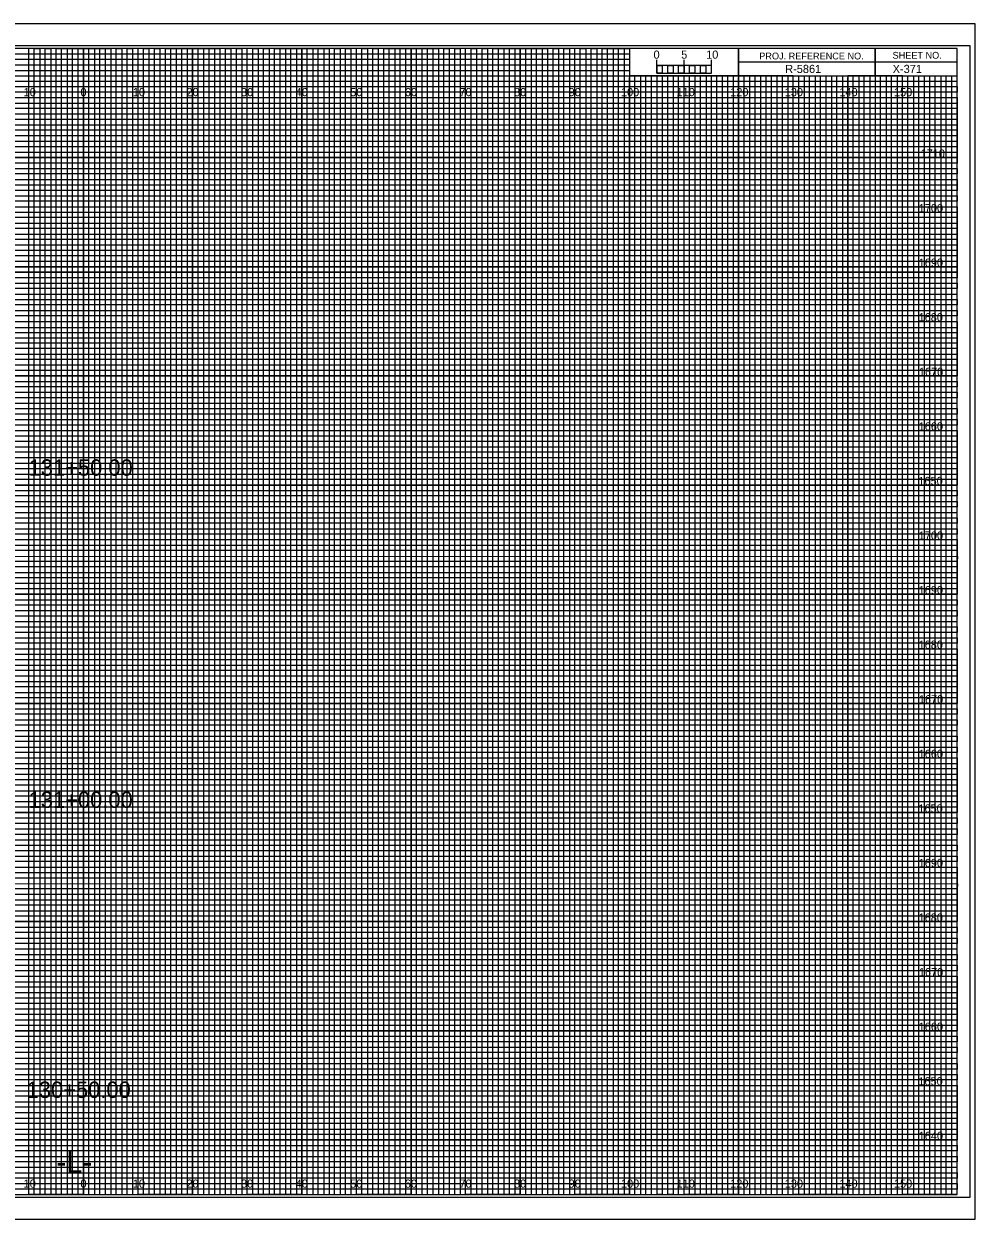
# Model space of a CAD drawing. Extents: x -13 to 323, y -5 to 2414.
# Drawn here: x 149.1 to 323.3, y 1535.5 to 1754.5 of the extents above; entities that cross this region are included whole.
import ezdxf

# ---------------------------------------------------------------- set-up
doc = ezdxf.new("R2010")
doc.units = 0
for name, color, linetype in [('Prop XS Alignment Label', 7, 'Continuous'), ('Prop XS Bar Scale Labels', 7, 'Continuous'), ('Prop XS Elevation Labels', 7, 'Continuous'), ('Prop XS Offset Labels', 7, 'Continuous'), ('Prop XS Project Number', 7, 'Continuous'), ('Prop XS Sheet Number', 7, 'Continuous'), ('Prop XS Station Labels', 7, 'Continuous'), ('Sheet Cross Section CELL', 7, 'Continuous'), ('Sheet Cross Section Grid Major CELL', 7, 'Continuous'), ('Sheet Cross Section Grid Middle CELL', 7, 'Continuous'), ('Sheet Cross Section Grid Minor 1 CELL', 7, 'Continuous'), ('Sheet Cross Section Grid Minor 2 CELL', 7, 'Continuous'), ('Sheet Cross Section Scale CELL', 7, 'Continuous'), ('Sheet Cutting Line CELL', 7, 'Continuous'), ('Sheet DOT Grid CELL', 7, 'Continuous'), ('Sheet Plot Border Inside CELL', 7, 'Continuous'), ('Sheet Plot Border Outside CELL', 7, 'Continuous')]:
    doc.layers.add(name, color=color, linetype=linetype)

msp = doc.modelspace()

# ---------------------------------------------------------------- linework, layer by layer
at = {"layer": 'Sheet Cross Section CELL'}
for p, q in [((305, 1750), (305, 1745)), ((305, 1745), (305, 1750)), ((280, 1747.5), (280, 1745)), ((320, 1747.49), (280, 1747.49)), ((280, 1745), (320, 1745))]:
    msp.add_line(p, q, dxfattribs=at)
for points in [[(320, 1750), (0, 1750), (0, 1540), (320, 1540)], [(280, 1750), (260, 1750), (260, 1745.03), (280, 1745.03)], [(320, 1750), (280, 1750), (280, 1745), (320, 1745)]]:
    msp.add_lwpolyline(points, close=True, dxfattribs=at)
at = {"layer": 'Sheet Cross Section Grid Major CELL'}
for p, q in [((150, 1750), (140, 1750)), ((150, 1540), (150, 1750)), ((170, 1750), (160, 1750)), ((160, 1750), (160, 1540)), ((170, 1540), (170, 1750)), ((190, 1750), (180, 1750)), ((180, 1750), (180, 1540)), ((190, 1540), (190, 1750)), ((210, 1750), (200, 1750)), ((200, 1750), (200, 1540)), ((210, 1540), (210, 1750)), ((230, 1750), (220, 1750)), ((220, 1750), (220, 1540)), ((230, 1540), (230, 1750)), ((250, 1750), (240, 1750)), ((240, 1750), (240, 1540)), ((250, 1540), (250, 1750)), ((260, 1750), (260, 1540)), ((270, 1540), (270, 1745)), ((290, 1745), (280, 1745)), ((280, 1745), (280, 1540)), ((290, 1540), (290, 1745)), ((310, 1745), (300, 1745)), ((300, 1745), (300, 1540)), ((310, 1540), (310, 1745)), ((160, 1540), (150, 1540)), ((180, 1540), (170, 1540)), ((200, 1540), (190, 1540)), ((220, 1540), (210, 1540)), ((240, 1540), (230, 1540)), ((260, 1540), (250, 1540)), ((280, 1540), (270, 1540)), ((300, 1540), (290, 1540)), ((320, 1540), (310, 1540)), ((320, 1540), (320, 1540))]:
    msp.add_line(p, q, dxfattribs=at)
for points in [[(0, 1740), (320, 1740), (320, 1730), (0, 1730)], [(0, 1720), (320, 1720), (320, 1710), (0, 1710)], [(0, 1700), (320, 1700), (320, 1690), (0, 1690)], [(0, 1680), (320, 1680), (320, 1670), (0, 1670)], [(0, 1660), (320, 1660), (320, 1650), (0, 1650)], [(0, 1640), (320, 1640), (320, 1630), (0, 1630)], [(0, 1620), (320, 1620), (320, 1610), (0, 1610)], [(0, 1600), (320, 1600), (320, 1590), (0, 1590)], [(0, 1580), (320, 1580), (320, 1570), (0, 1570)], [(0, 1560), (320, 1560), (320, 1550), (0, 1550)]]:
    msp.add_lwpolyline(points, dxfattribs=at)
at = {"layer": 'Sheet Cross Section Grid Middle CELL'}
for points in [[(145, 1540), (155, 1540), (155, 1750), (165, 1750), (165, 1540), (175, 1540), (175, 1750), (185, 1750), (185, 1540), (195, 1540), (195, 1750), (205, 1750), (205, 1540), (215, 1540), (215, 1750), (225, 1750), (225, 1540), (235, 1540), (235, 1750), (245, 1750), (245, 1540), (255, 1540), (255, 1750), (259.93, 1750), (260, 1750), (260, 1745), (264.99, 1745), (264.99, 1540), (275, 1540), (275, 1745), (285, 1745), (285, 1540), (295, 1540), (295, 1745), (305, 1745), (305, 1540), (315, 1540), (315, 1745)], [(0, 1745), (275, 1745)], [(0, 1725), (320, 1725), (320, 1735), (0, 1735)], [(0, 1705), (320, 1705), (320, 1715), (0, 1715)], [(0, 1685), (320, 1685), (320, 1695), (0, 1695)], [(0, 1665), (320, 1665), (320, 1675), (0, 1675)], [(0, 1645), (320, 1645), (320, 1655), (0, 1655)], [(0, 1625), (320, 1625), (320, 1635), (0, 1635)], [(0, 1605), (320, 1605), (320, 1615), (0, 1615)], [(0, 1585), (320, 1585), (320, 1595), (0, 1595)], [(0, 1565), (320, 1565), (320, 1575), (0, 1575)], [(0, 1545), (320, 1545), (320, 1555), (0, 1555)]]:
    msp.add_lwpolyline(points, dxfattribs=at)
at = {"layer": 'Sheet Cross Section Grid Minor 1 CELL'}
for p, q in [((0, 1749), (260, 1749)), ((260, 1747.98), (0, 1747.98)), ((260, 1749), (260, 1747.98)), ((0, 1747), (260, 1747)), ((260, 1745.89), (0, 1745.89)), ((260, 1747), (260, 1745.89)), ((0, 1744), (320, 1744))]:
    msp.add_line(p, q, dxfattribs=at)
for points in [[(0, 1743), (270, 1743), (320, 1743), (320, 1742), (0, 1742)], [(0, 1741), (320, 1741), (320, 1739), (0, 1739)], [(0, 1738), (320, 1738), (320, 1737), (0, 1736.98)], [(0, 1736), (320, 1736), (320, 1734), (0, 1734)], [(0, 1733), (320, 1733), (320, 1732), (0, 1732)], [(0, 1731), (320, 1731), (320, 1729), (0, 1729)], [(0, 1728), (320, 1728), (320, 1727), (0, 1727)], [(0, 1726), (320, 1726), (320, 1724), (0, 1724)], [(0, 1723), (320, 1723), (320, 1722), (0, 1722)], [(0, 1721), (320, 1721), (320, 1719), (0, 1719)], [(0, 1718), (320, 1718), (320, 1717), (0, 1717)], [(0, 1716), (320, 1716), (320, 1713.95), (320, 1713), (320, 1712), (0, 1712)], [(0, 1714), (320, 1714), (320, 1713), (0, 1713)], [(0, 1711), (320, 1711), (320, 1709), (0, 1709.03)], [(0, 1709.03), (320, 1709), (320, 1708), (0, 1708)], [(0, 1707), (320, 1707), (320, 1706), (0, 1706)], [(0, 1704), (320, 1704), (320, 1703), (0, 1703)], [(0, 1702), (320, 1702), (320, 1701), (0, 1701)], [(-0.07, 1698.89), (320, 1698.89), (320, 1697.88), (-0.07, 1697.88)], [(0, 1697), (320, 1697), (320, 1696), (0, 1696)], [(0, 1694), (320, 1694), (320, 1693), (0, 1693)], [(0, 1692), (320, 1692), (320, 1691), (0, 1691)], [(0, 1689), (320, 1689), (320, 1688), (0, 1688)], [(0, 1687), (320, 1687), (320, 1686), (0, 1686)], [(0, 1684), (320, 1684), (320, 1683), (0, 1683)], [(0, 1682), (320, 1682), (320, 1681), (0, 1681)], [(0, 1679), (320, 1679), (319.99, 1677.98), (0, 1678)], [(0, 1677), (320, 1677), (320, 1676), (0, 1676)], [(0, 1674), (320, 1674), (320, 1673), (0, 1673)], [(0, 1672), (320, 1672), (320, 1671), (0, 1671)], [(0, 1669), (320, 1669), (320, 1668), (0, 1668)], [(0, 1667), (320, 1667), (320, 1666), (0, 1666)], [(0, 1664), (320, 1664), (320, 1663), (0, 1663)], [(0, 1662), (320, 1662), (320, 1661), (0, 1661)], [(0, 1659), (320, 1659), (320, 1658), (0, 1658)], [(0, 1656.99), (320.07, 1656.91), (320, 1656), (0, 1656)], [(0, 1654), (320, 1654), (320, 1653), (0, 1653)], [(0, 1652), (320, 1652), (320, 1651), (0, 1651)], [(0, 1649), (320, 1649), (320, 1648), (0, 1648)], [(0, 1647), (320, 1647), (320, 1646), (0, 1646)], [(0, 1644), (320, 1644), (320, 1643), (0, 1643)], [(0, 1642), (320, 1642), (320, 1641), (0, 1641)], [(0, 1639), (320, 1639), (320, 1638), (0, 1638)], [(0, 1637), (320, 1637), (320, 1636), (0, 1636)], [(0, 1634), (320, 1634), (320, 1633), (0, 1633)], [(0, 1632), (320, 1632), (320, 1631), (0, 1631)], [(0, 1629), (320, 1629), (320, 1628), (0, 1628)], [(0, 1627), (320, 1627), (320, 1626), (0, 1626)], [(0, 1624), (320, 1624), (320, 1623), (0, 1623)], [(0, 1622), (320, 1622), (320, 1621), (0, 1621)], [(0, 1619), (320, 1619), (319.99, 1617.98), (0, 1618)], [(0, 1617), (320, 1617), (320, 1616), (0, 1616)], [(0, 1614), (320, 1614), (320, 1613), (0, 1613)], [(0, 1612), (320, 1612), (320, 1611), (0, 1611)], [(0, 1609), (320, 1609), (320, 1608), (0, 1608)], [(0, 1607), (320, 1607), (320, 1606), (0, 1606)], [(0, 1604), (320, 1604), (320, 1603), (0, 1603)], [(0, 1602), (320, 1602), (320, 1601), (0, 1601)], [(0, 1599), (320, 1599), (320, 1598), (0, 1598)], [(0, 1596.99), (320.07, 1596.91), (320, 1596), (0, 1596)], [(0, 1594), (320, 1594), (320, 1593), (0, 1593)], [(0, 1592), (320, 1592), (320, 1591), (0, 1591)], [(0, 1589), (320, 1589), (320, 1588), (0, 1588)], [(0, 1587), (320, 1587), (320, 1586), (0, 1586)], [(0, 1584), (320, 1584), (320, 1583), (0, 1583)], [(0, 1582), (320, 1582), (320, 1581), (0, 1581)], [(0, 1579), (320, 1579), (320, 1578), (0, 1578)], [(0, 1577), (320, 1577), (320, 1576), (0, 1576)], [(0, 1574), (320, 1574), (320, 1573), (0, 1573)], [(0, 1572), (320, 1572), (320, 1571), (0, 1571)], [(0, 1569), (320, 1569), (320, 1568), (0, 1568)], [(0, 1567), (320, 1567), (320, 1566), (0, 1566)], [(0, 1564), (320, 1564), (320, 1563), (0, 1563)], [(0, 1562), (320, 1562), (320, 1561), (0, 1561)], [(0, 1559), (320, 1559), (320, 1558), (0, 1558)], [(0, 1557), (320, 1557), (320, 1556), (0, 1556)], [(0, 1554), (320, 1554), (320, 1553), (0, 1553)], [(0, 1552), (320, 1552), (320, 1551), (0, 1551)], [(0, 1549), (320, 1549), (320, 1548), (0, 1548)], [(0, 1547), (320, 1547), (320, 1546), (0, 1546)], [(0, 1544), (320, 1544), (320, 1543), (0, 1543)], [(0, 1542), (320, 1542), (320, 1541), (0, 1541)]]:
    msp.add_lwpolyline(points, dxfattribs=at)
at = {"layer": 'Sheet Cross Section Grid Minor 2 CELL'}
for p, q in [((267, 1745), (266.01, 1745)), ((266.01, 1745), (266.01, 1540)), ((267, 1540), (267, 1745)), ((269, 1745), (268, 1745)), ((268, 1745), (268, 1540)), ((269, 1540), (269, 1745)), ((266.01, 1540), (265, 1540)), ((268, 1540), (267, 1540))]:
    msp.add_line(p, q, dxfattribs=at)
for points in [[(150, 1540), (151, 1540), (151, 1750), (152, 1750), (152, 1540)], [(152, 1540), (153, 1540), (153, 1750), (154, 1750), (154, 1540)], [(155, 1540), (156, 1540), (156, 1750), (157, 1750), (157, 1540)], [(157, 1540), (158, 1540), (158, 1750), (159, 1750), (159, 1540)], [(160, 1540), (161, 1540), (161, 1750), (162, 1750), (162, 1540)], [(162, 1540), (163, 1540), (163, 1750), (164, 1750), (164, 1540)], [(165, 1540), (166, 1540), (166, 1750), (167, 1750), (167, 1540)], [(167, 1540), (168, 1540), (168, 1750), (169, 1750), (169, 1540)], [(170, 1540), (171, 1540), (171, 1750), (172, 1750), (172, 1540)], [(172, 1540), (173, 1540), (173, 1750), (174, 1750), (174, 1540)], [(175, 1540), (176, 1540), (176, 1750), (177, 1750), (177, 1540)], [(177, 1540), (178, 1540), (178, 1750), (179, 1750), (179, 1540)], [(180, 1540), (181, 1540), (181, 1750), (182, 1750), (182, 1540)], [(182, 1540), (183, 1540), (183, 1750), (184, 1750), (184, 1540)], [(185, 1540), (186, 1540), (186, 1750), (187, 1750), (187, 1540)], [(187, 1540), (188, 1540), (188, 1750), (189, 1750), (189, 1540)], [(190, 1540), (191, 1540), (191, 1750), (192, 1750), (192, 1540)], [(192, 1540), (193, 1540), (193, 1750), (194, 1750), (194, 1540)], [(195, 1540), (196, 1540), (196, 1750), (197, 1750), (197, 1540)], [(197, 1540), (198, 1540), (198, 1750), (199, 1750), (199, 1540)], [(200, 1540), (201, 1540), (201, 1750), (202, 1750), (202, 1540)], [(202, 1540), (203, 1540), (203, 1750), (204, 1750), (204, 1540)], [(205, 1540), (206, 1540), (206, 1750), (207, 1750), (207, 1540)], [(207, 1540), (208, 1540), (208, 1750), (209, 1750), (209, 1540)], [(210, 1540), (211, 1540), (211, 1750), (212, 1750), (212, 1540)], [(212, 1540), (213, 1540), (213, 1750), (214, 1750), (214, 1540)], [(215, 1540), (216, 1540), (216, 1750), (217, 1750), (217, 1540)], [(217, 1540), (218, 1540), (218, 1750), (219, 1750), (219, 1540)], [(220, 1540), (221, 1540), (221, 1750), (222, 1750), (222, 1540)], [(222, 1540), (223, 1540), (223, 1750), (224, 1750), (224, 1540)], [(225, 1540), (226, 1540), (226, 1750), (227, 1750), (227, 1540)], [(227, 1540), (228, 1540), (228, 1750), (229, 1750), (229, 1540)], [(230, 1540), (231, 1540), (231, 1750), (232, 1750), (232, 1540)], [(232, 1540), (233, 1540), (233, 1750), (234, 1750), (234, 1540)], [(235, 1540), (236, 1540), (236, 1750), (237, 1750), (237, 1540)], [(237, 1540), (238, 1540), (238, 1750), (239, 1750), (239, 1540)], [(240, 1540), (241, 1540), (241, 1750), (242, 1750), (242, 1540)], [(242, 1540), (243, 1540), (243, 1750), (244, 1750), (244, 1540)], [(245, 1540), (246, 1540), (246, 1750), (247, 1750), (247, 1540)], [(247, 1540), (248, 1540), (248, 1750), (249, 1750), (249, 1540)], [(250, 1540), (251, 1540), (251, 1750), (252, 1750), (252, 1540)], [(252, 1540), (253, 1540), (253, 1750), (254, 1750), (254, 1540)], [(255, 1540), (256, 1540), (256, 1750), (257, 1750), (257, 1540)], [(257, 1540), (258, 1540), (258, 1750), (259, 1750), (259, 1540)], [(260, 1540), (261, 1540), (261, 1745), (262.02, 1745), (262.02, 1540)], [(262, 1540), (263, 1540), (263, 1745), (263.99, 1745), (263.99, 1540)], [(270, 1540), (270.98, 1540), (270.98, 1745), (272, 1745), (272, 1540)], [(272, 1540), (273, 1540), (273, 1745), (274.05, 1745), (274.05, 1540)], [(275, 1540), (276, 1540), (276, 1745), (277, 1745), (277, 1540)], [(277, 1540), (278, 1540), (278, 1745), (279, 1745), (279, 1540)], [(280, 1540), (281, 1540), (281, 1745), (282, 1745), (282, 1540)], [(282, 1540), (283, 1540), (283, 1745), (284, 1745), (284, 1540)], [(285, 1540), (286, 1540), (286, 1745), (287, 1745), (287, 1540)], [(287, 1540), (288, 1540), (288, 1745), (289, 1745), (289, 1540)], [(290, 1540), (291, 1540), (291, 1745), (292, 1745), (292, 1540)], [(292, 1540), (293, 1540), (293, 1745), (294, 1745), (294, 1540)], [(295, 1540), (296, 1540), (296, 1745), (297, 1745), (297, 1540)], [(297, 1540), (298, 1540), (298, 1745), (299, 1745), (299, 1540)], [(300, 1540), (301, 1540), (301, 1745), (302, 1745), (302, 1540)], [(302, 1540), (303, 1540), (303, 1745), (304, 1745), (304, 1540)], [(305, 1540), (306, 1540), (306, 1745), (307, 1745), (307, 1540)], [(307, 1540), (308, 1540), (308, 1745), (309, 1745), (309, 1540)], [(310, 1540), (311, 1540), (311, 1745), (312, 1745), (312, 1540)], [(312, 1540), (313, 1540), (313, 1745), (314, 1745), (314, 1540)], [(315, 1540), (316, 1540), (316, 1745), (317, 1745), (317, 1540)], [(317, 1540), (318, 1540), (318, 1745), (319, 1745), (319, 1540)]]:
    msp.add_lwpolyline(points, dxfattribs=at)
at = {"layer": 'Sheet Cross Section Scale CELL'}
for p, q in [((265, 1745.49), (265, 1747.9)), ((265, 1746.9), (265, 1747.9)), ((270, 1745.49), (270, 1747.9)), ((275, 1745.49), (275, 1747.9)), ((275, 1746.9), (275, 1747.9))]:
    msp.add_line(p, q, dxfattribs=at)
for points in [[(275, 1746.9), (265, 1746.9), (265, 1745.49), (275, 1745.49)], [(265, 1746.9), (266, 1746.9), (266, 1745.49), (265, 1745.49)], [(267, 1746.9), (268, 1746.9), (268, 1745.49), (267, 1745.49)], [(269, 1746.9), (270, 1746.9), (270, 1745.49), (269, 1745.49)], [(271, 1746.9), (272, 1746.9), (272, 1745.49), (271, 1745.49)], [(273, 1746.9), (274, 1746.9), (274, 1745.49), (273, 1745.49)]]:
    msp.add_lwpolyline(points, close=True, dxfattribs=at)
at = {"layer": 'Sheet Cutting Line CELL'}
for p, q in [((323.3, 1754.5), (-13.4, 1754.5)), ((-13.4, 1535.5), (323.3, 1535.5))]:
    msp.add_line(p, q, dxfattribs=at)
at = {"layer": 'Sheet DOT Grid CELL'}
for p, q in [((150, 1540), (150, 1750)), ((160, 1540), (160, 1750)), ((170, 1540), (170, 1750)), ((180, 1540), (180, 1750)), ((190, 1540), (190, 1750)), ((200, 1540), (200, 1750)), ((210, 1540), (210, 1750)), ((220, 1540), (220, 1750)), ((230, 1540), (230, 1750)), ((240, 1540), (240, 1750)), ((250, 1540), (250, 1750)), ((260, 1540), (260, 1744.69)), ((270, 1540), (270, 1744.69)), ((280, 1540), (280, 1744.69)), ((290, 1540), (290, 1744.69)), ((300, 1540), (300, 1744.69)), ((310, 1540), (310, 1744.69)), ((0, 1740), (320, 1740)), ((0, 1730), (320, 1730)), ((0, 1720), (320, 1720)), ((0, 1710), (320, 1710)), ((0, 1700), (320, 1700)), ((0, 1690), (320, 1690)), ((0, 1680), (320, 1680)), ((0, 1670), (320, 1670)), ((0, 1660), (320, 1660)), ((0, 1650), (320, 1650)), ((0, 1640), (320, 1640)), ((0, 1630), (320, 1630)), ((0, 1620), (320, 1620)), ((0, 1610), (320, 1610)), ((0, 1600), (320, 1600)), ((0, 1590), (320, 1590)), ((0, 1580), (320, 1580)), ((0, 1570), (320, 1570)), ((0, 1560), (320, 1560)), ((0, 1550), (320, 1550))]:
    msp.add_line(p, q, dxfattribs=at)
at = {"layer": 'Sheet Plot Border Inside CELL'}
msp.add_lwpolyline([(-10.8, 1539.5), (322.4, 1539.5), (322.4, 1750.5), (-10.8, 1750.5)], close=True, dxfattribs=at)
at = {"layer": 'Sheet Plot Border Outside CELL'}
msp.add_lwpolyline([(-13.4, 1535.5), (323.3, 1535.5), (323.3, 1754.5), (-13.4, 1754.5)], close=True, dxfattribs=at)

# ---------------------------------------------------------------- texts
at = {"layer": 'Prop XS Alignment Label'}
msp.add_text('-L-', height=4, dxfattribs=at).set_placement((155.06, 1544))
at = {"layer": 'Prop XS Bar Scale Labels'}
for s, p in [('5', (269.47, 1748.12)), ('10', (274.04, 1748.12))]:
    msp.add_text(s, height=1.5, dxfattribs=at).set_placement(p)
at = {"layer": 'Prop XS Elevation Labels'}
for s, p in [('1710', (313.31, 1730)), ('1700', (312.98, 1720)), ('1690', (312.97, 1710)), ('1680', (312.95, 1700)), ('1670', (313, 1690)), ('1660', (312.97, 1680)), ('1650', (312.92, 1670)), ('1700', (312.98, 1660)), ('1690', (312.97, 1650)), ('1680', (312.95, 1640)), ('1670', (313, 1630)), ('1660', (312.97, 1620)), ('1650', (312.92, 1610)), ('1690', (312.97, 1600)), ('1680', (312.95, 1590)), ('1670', (313, 1580)), ('1660', (312.97, 1570)), ('1650', (312.92, 1560)), ('1640', (312.97, 1550))]:
    msp.add_text(s, height=1.5, dxfattribs=at).set_placement(p)
at = {"layer": 'Prop XS Offset Labels'}
for s, p in [('10', (149.04, 1741.25)), ('0', (159.45, 1741.25)), ('0', (159.45, 1741.25)), ('10', (169.04, 1741.25)), ('20', (178.86, 1741.25)), ('30', (188.86, 1741.25)), ('40', (198.86, 1741.25)), ('50', (208.86, 1741.25)), ('60', (218.86, 1741.25)), ('70', (228.86, 1741.25)), ('80', (238.86, 1741.25)), ('90', (248.86, 1741.25)), ('100', (258.44, 1741.25)), ('110', (268.62, 1741.25)), ('120', (278.44, 1741.25)), ('130', (288.44, 1741.25)), ('140', (298.44, 1741.25)), ('150', (308.44, 1741.25)), ('10', (149.04, 1541.25)), ('0', (159.45, 1541.25)), ('0', (159.45, 1541.25)), ('10', (169.04, 1541.25)), ('20', (178.86, 1541.25)), ('30', (188.86, 1541.25)), ('40', (198.86, 1541.25)), ('50', (208.86, 1541.25)), ('60', (218.86, 1541.25)), ('70', (228.86, 1541.25)), ('80', (238.86, 1541.25)), ('90', (248.86, 1541.25)), ('100', (258.44, 1541.25)), ('110', (268.62, 1541.25)), ('120', (278.44, 1541.25)), ('130', (288.44, 1541.25)), ('140', (298.44, 1541.25)), ('150', (308.44, 1541.25))]:
    msp.add_text(s, height=1.5, dxfattribs=at).set_placement(p)
at = {"layer": 'Prop XS Project Number'}
msp.add_text('R-5861', height=1.5, dxfattribs=at).set_placement((288.53, 1745.5))
at = {"layer": 'Prop XS Sheet Number'}
msp.add_text('X-371', height=1.5, dxfattribs=at).set_placement((308.21, 1745.5))
at = {"layer": 'Prop XS Station Labels'}
for s, p in [('131+50.00', (149.95, 1671.71)), ('131+00.00', (149.95, 1610.84)), ('130+50.00', (149.59, 1557.7))]:
    msp.add_text(s, height=3, dxfattribs=at).set_placement(p)
at = {"layer": 'Sheet Cross Section CELL'}
for s, p in [('PROJ. REFERENCE NO.', (283.77, 1747.99)), ('SHEET NO.', (308.19, 1748.12))]:
    msp.add_text(s, height=1.25, dxfattribs=at).set_placement(p)
at = {"layer": 'Sheet Cross Section Scale CELL'}
msp.add_text('0', height=1.5, dxfattribs=at).set_placement((264.41, 1748.12))

doc.saveas('drawing.dxf')
